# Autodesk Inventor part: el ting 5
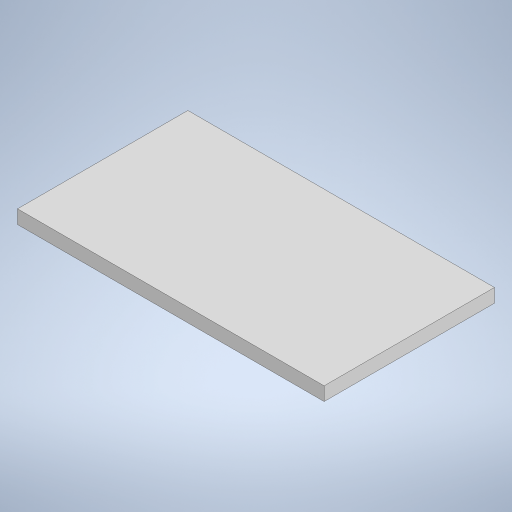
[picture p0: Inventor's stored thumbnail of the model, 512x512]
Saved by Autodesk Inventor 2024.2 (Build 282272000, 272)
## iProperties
Created: 2024-05
Part Number: el ting 5
Material: Generic
Document SubType Name: Modeling
Designer: Karsten
Density: 1 g/cm^3
Appearance: Default
Author: Karsten
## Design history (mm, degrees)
sketch "Sketch1"
  geometry: L1 (0, 0)-(-45, 0); L2 (-45, 0)-(-45, -25); L3 (-45, -25)-(0, -25); L4 (0, -25)-(0, 0)
  constraints: 8 end point, 2 parallel, 1 horizontal, 1 perpendicular
  dimensions: "d0" = 45 distance of L3.end L2.end; "d1" = 25 distance of L2.end L1.end
extrude "Extrusion1" new body sketch "Sketch1" distance "d2" = 2; taper "d3" = 0 deg
body "Solid1"
